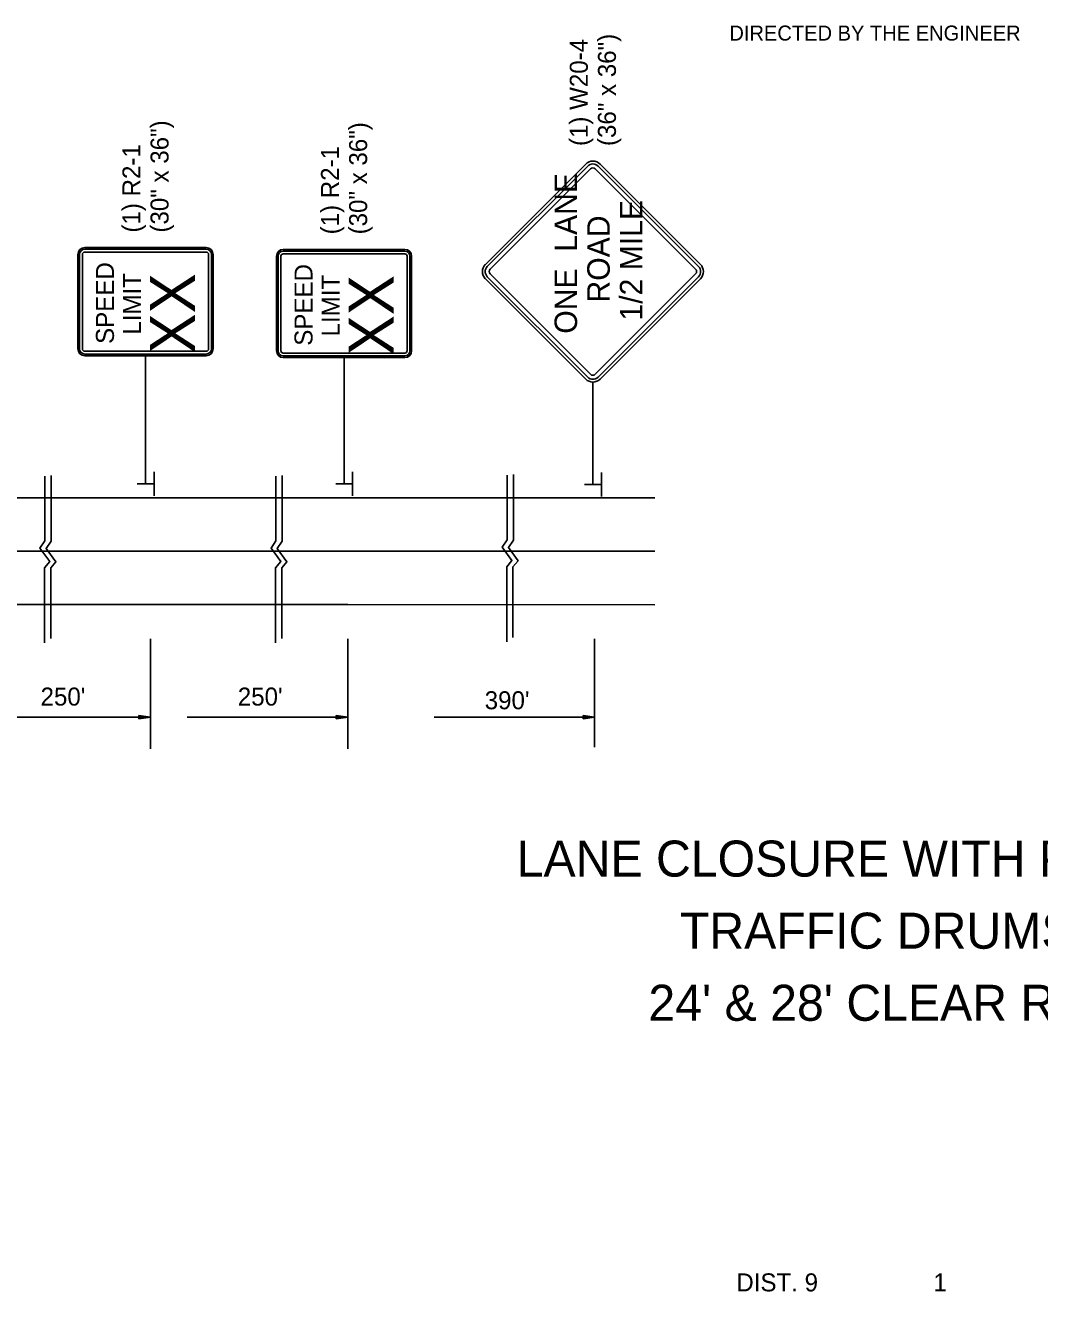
# Model space of a CAD drawing. Extents: x 1930579 to 1939784, y 596179 to 597522.
# Drawn here: x 1937952 to 1938289.6, y 596238.1 to 596659.7 of the extents above; entities that cross this region are included whole.
import ezdxf

# ---------------------------------------------------------------- set-up
doc = ezdxf.new("R2010")
doc.units = 0
for name, color, linetype in [('Default', 7, 'Continuous'), ('P_TC_Signs_Permanent', 7, 'Continuous'), ('P_TC_Signs_Temporary', 7, 'Continuous'), ('R_Annotation', 7, 'Continuous')]:
    doc.layers.add(name, color=color, linetype=linetype)

msp = doc.modelspace()

# ---------------------------------------------------------------- linework, layer by layer
at = {"layer": 'Default'}
for p, q in [((1937994.84, 596511.1), (1937994.84, 596503.09)), ((1938060.94, 596511.04), (1938060.94, 596503.03)), ((1938143.76, 596510.87), (1938143.76, 596502.87)), ((1937994.72, 596507.12), (1937989.26, 596507.12)), ((1938060.82, 596507.06), (1938055.35, 596507.06)), ((1938143.65, 596506.89), (1938138.18, 596506.89)), ((1937444.6, 596502.47), (1938059.31, 596502.42)), ((1938059.31, 596502.42), (1938161.51, 596502.41)), ((1937443.89, 596484.68), (1938161.51, 596484.63)), ((1937444.38, 596466.89), (1938059.31, 596466.85)), ((1938059.31, 596466.85), (1938161.51, 596466.83)), ((1937993.66, 596418.83), (1937993.66, 596455.43)), ((1938059.31, 596418.83), (1938059.31, 596455.43)), ((1938141.5, 596419.4), (1938141.5, 596455.43)), ((1937993.66, 596429.42), (1937940.26, 596429.42)), ((1937989.82, 596429.99), (1937993.66, 596429.42)), ((1937989.82, 596429.99), (1937989.82, 596428.84)), ((1937989.82, 596429.9), (1937993.02, 596429.42)), ((1937989.82, 596429.8), (1937992.36, 596429.42)), ((1937989.82, 596429.7), (1937991.72, 596429.42)), ((1937989.82, 596429.6), (1937991.07, 596429.42)), ((1937989.82, 596429.51), (1937990.43, 596429.42)), ((1937989.82, 596428.84), (1937993.66, 596429.42)), ((1937989.82, 596429.23), (1937991.07, 596429.42)), ((1937989.82, 596429.04), (1937992.36, 596429.42)), ((1937989.82, 596428.94), (1937993.02, 596429.42)), ((1937989.82, 596429.13), (1937991.72, 596429.42)), ((1937989.82, 596429.33), (1937990.43, 596429.42)), ((1938059.31, 596429.42), (1938005.91, 596429.42)), ((1938055.48, 596429.99), (1938059.31, 596429.42)), ((1938055.48, 596429.99), (1938055.48, 596428.84)), ((1938055.48, 596429.9), (1938058.67, 596429.42)), ((1938055.48, 596429.8), (1938058.01, 596429.42)), ((1938055.48, 596429.7), (1938057.37, 596429.42)), ((1938055.48, 596429.6), (1938056.72, 596429.42)), ((1938055.48, 596429.51), (1938056.08, 596429.42)), ((1938055.48, 596428.84), (1938059.31, 596429.42)), ((1938055.48, 596429.23), (1938056.72, 596429.42)), ((1938055.48, 596429.04), (1938058.01, 596429.42)), ((1938055.48, 596428.94), (1938058.67, 596429.42)), ((1938055.48, 596429.13), (1938057.37, 596429.42)), ((1938055.48, 596429.33), (1938056.08, 596429.42)), ((1938141.5, 596429.42), (1938088.1, 596429.42)), ((1938137.66, 596429.99), (1938141.5, 596429.42)), ((1938137.66, 596429.99), (1938137.66, 596428.84)), ((1938137.66, 596429.9), (1938140.86, 596429.42)), ((1938137.66, 596429.8), (1938140.2, 596429.42)), ((1938137.66, 596429.7), (1938139.56, 596429.42)), ((1938137.66, 596429.6), (1938138.91, 596429.42)), ((1938137.66, 596429.51), (1938138.27, 596429.42)), ((1938137.66, 596428.84), (1938141.5, 596429.42)), ((1938137.66, 596429.23), (1938138.91, 596429.42)), ((1938137.66, 596429.04), (1938140.2, 596429.42)), ((1938137.66, 596428.94), (1938140.86, 596429.42)), ((1938137.66, 596429.13), (1938139.56, 596429.42)), ((1938137.66, 596429.33), (1938138.27, 596429.42))]:
    msp.add_line(p, q, dxfattribs=at)
for points in [[(1937958.53, 596509.62), (1937958.53, 596488.1), (1937956.87, 596485.63), (1937960.11, 596481.2), (1937958.4, 596479.15), (1937958.4, 596454.12)], [(1937960.57, 596509.82), (1937960.57, 596488.01), (1937958.91, 596485.54), (1937962.15, 596481.11), (1937960.45, 596479.07), (1937960.44, 596455.56)], [(1938035.43, 596509.62), (1938035.43, 596488.1), (1938033.77, 596485.63), (1938037.01, 596481.2), (1938035.3, 596479.15), (1938035.3, 596454.12)], [(1938037.48, 596509.82), (1938037.48, 596488.01), (1938035.82, 596485.54), (1938039.05, 596481.11), (1938037.35, 596479.07), (1938037.34, 596455.56)], [(1938112.41, 596509.96), (1938112.41, 596488.44), (1938110.75, 596485.97), (1938113.98, 596481.54), (1938112.28, 596479.49), (1938112.27, 596454.47)], [(1938114.45, 596510.16), (1938114.45, 596488.35), (1938112.79, 596485.88), (1938116.03, 596481.45), (1938114.32, 596479.41), (1938114.32, 596455.91)]]:
    msp.add_lwpolyline(points, dxfattribs=at)
at = {"layer": 'P_TC_Signs_Permanent'}
for p, q in [((1938012.24, 596585.74), (1937971.74, 596585.74)), ((1938012.24, 596585.17), (1937971.74, 596585.17)), ((1938078.34, 596585.13), (1938037.84, 596585.13)), ((1937969.49, 596583.49), (1937969.49, 596551.99)), ((1937970.05, 596583.49), (1937970.05, 596551.99)), ((1937970.99, 596583.49), (1937970.99, 596551.99)), ((1938012.24, 596584.24), (1937971.74, 596584.24)), ((1938012.99, 596551.99), (1938012.99, 596583.49)), ((1938013.93, 596551.99), (1938013.93, 596583.49)), ((1938014.49, 596551.99), (1938014.49, 596583.49)), ((1938035.59, 596582.88), (1938035.59, 596551.38)), ((1938036.15, 596582.88), (1938036.15, 596551.38)), ((1938037.09, 596582.88), (1938037.09, 596551.38)), ((1938078.34, 596584.57), (1938037.84, 596584.57)), ((1938078.34, 596583.63), (1938037.84, 596583.63)), ((1938079.09, 596551.38), (1938079.09, 596582.88)), ((1938080.03, 596551.38), (1938080.03, 596582.88)), ((1938080.59, 596551.38), (1938080.59, 596582.88)), ((1937971.74, 596551.24), (1938012.24, 596551.24)), ((1937971.74, 596550.3), (1938012.24, 596550.3)), ((1937971.74, 596549.74), (1938012.24, 596549.74)), ((1938037.84, 596550.63), (1938078.34, 596550.63)), ((1938037.84, 596549.7), (1938078.34, 596549.7)), ((1938037.84, 596549.13), (1938078.34, 596549.13))]:
    msp.add_line(p, q, dxfattribs=at)
for centre, radius, start, end in [((1937971.74, 596583.49), 2.25, 90, 180), ((1937971.74, 596583.49), 1.69, 90, 180), ((1938012.24, 596583.49), 2.25, 360, 90), ((1938012.24, 596583.49), 1.69, 360, 90), ((1938037.84, 596582.88), 2.25, 90, 180), ((1938078.34, 596582.88), 2.25, 360, 90), ((1937971.74, 596583.49), 0.75, 90, 180), ((1938012.24, 596583.49), 0.75, 360, 90), ((1938037.84, 596582.88), 1.69, 90, 180), ((1938037.84, 596582.88), 0.75, 90, 180), ((1938078.34, 596582.88), 1.69, 360, 90), ((1938078.34, 596582.88), 0.75, 360, 90), ((1937971.74, 596551.99), 2.25, 180, 270), ((1937971.74, 596551.99), 1.69, 180, 270), ((1937971.74, 596551.99), 0.75, 180, 270), ((1938012.24, 596551.99), 2.25, 270, 360), ((1938012.24, 596551.99), 1.69, 270, 360), ((1938012.24, 596551.99), 0.75, 270, 360), ((1938037.84, 596551.38), 2.25, 180, 270), ((1938037.84, 596551.38), 1.69, 180, 270), ((1938037.84, 596551.38), 0.75, 180, 270), ((1938078.34, 596551.38), 2.25, 270, 360), ((1938078.34, 596551.38), 1.69, 270, 360), ((1938078.34, 596551.38), 0.75, 270, 360)]:
    msp.add_arc(centre, radius, start, end, dxfattribs=at)
at = {"layer": 'P_TC_Signs_Temporary'}
for p, q in [((1938105.12, 596580.15), (1938138.53, 596613.56)), ((1938105.78, 596579.48), (1938139.19, 596612.89)), ((1938106.71, 596578.56), (1938140.12, 596611.97)), ((1938141.71, 596611.97), (1938175.12, 596578.56)), ((1938142.64, 596612.89), (1938176.05, 596579.48)), ((1938143.3, 596613.56), (1938176.71, 596580.15)), ((1938140.12, 596543.55), (1938106.71, 596576.96)), ((1938175.12, 596576.96), (1938141.71, 596543.55)), ((1938138.53, 596541.96), (1938105.12, 596575.37)), ((1938139.19, 596542.63), (1938105.78, 596576.04)), ((1938176.05, 596576.04), (1938142.64, 596542.63)), ((1938176.71, 596575.37), (1938143.3, 596541.96))]:
    msp.add_line(p, q, dxfattribs=at)
for centre, radius, start, end in [((1938140.91, 596611.17), 3.38, 45, 135), ((1938140.91, 596611.17), 2.44, 45, 135), ((1938140.91, 596611.17), 1.12, 45, 135), ((1938107.5, 596577.76), 3.38, 135, 225), ((1938107.5, 596577.76), 2.44, 135, 225), ((1938107.5, 596577.76), 1.13, 135, 225), ((1938174.32, 596577.76), 1.13, 315, 45), ((1938174.32, 596577.76), 2.44, 315, 45), ((1938174.32, 596577.76), 3.38, 315, 45), ((1938140.91, 596544.35), 1.12, 225, 315), ((1938140.91, 596544.35), 3.38, 225, 315), ((1938140.91, 596544.35), 2.44, 225, 315)]:
    msp.add_arc(centre, radius, start, end, dxfattribs=at)
at = {"layer": 'R_Annotation'}
for p, q in [((1937991.99, 596507.12), (1937991.99, 596549.74)), ((1938058.09, 596507.06), (1938058.09, 596549.13)), ((1938140.91, 596506.89), (1938140.91, 596540.97))]:
    msp.add_line(p, q, dxfattribs=at)

# ---------------------------------------------------------------- texts
at = {"layer": 'Default'}
for s, height, p in [("250'", 6, (1937957.06, 596433.25)), ("250'", 6, (1938022.71, 596433.25)), ("390'", 6, (1938104.9, 596432.02)), ('LANE CLOSURE WITH PORTABLE TRAFFIC SIGNAL SYSTEM &', 12, (1938115.55, 596376.3)), ('TRAFFIC DRUMS FOR HYDRODEMOLITION BRIDGES', 12, (1938169.88, 596352.3)), ("24' & 28' CLEAR ROADWAY ON THE BRIDGE DECKS", 12, (1938159.39, 596328.3))]:
    msp.add_text(s, height=height, rotation=360, dxfattribs=at).set_placement(p)
at = {"layer": 'P_TC_Signs_Permanent'}
for s, height, p in [('SPEED', 6, (1937981.49, 596553.67)), ('LIMIT', 6, (1937990.49, 596556.76)), ('XX', 15, (1938008.49, 596550.44)), ('SPEED', 6, (1938047.59, 596553.06)), ('LIMIT', 6, (1938056.59, 596556.15)), ('XX', 15, (1938074.59, 596549.83))]:
    msp.add_text(s, height=height, rotation=90, dxfattribs=at).set_placement(p)
at = {"layer": 'P_TC_Signs_Temporary'}
for s, p in [('ONE  LANE', (1938135.66, 596557.06)), ('1/2 MILE', (1938157.41, 596561.45)), ('ROAD', (1938146.54, 596567.45))]:
    msp.add_text(s, height=7.5, rotation=90, dxfattribs=at).set_placement(p)
at = {"layer": 'R_Annotation'}
for s, height, rotation, p in [('DIRECTED BY THE ENGINEER', 5, 360, (1938186.35, 596654.66)), ('(1) W20-4', 6, 90, (1938139.23, 596619.55)), ('(36" x 36")', 6, 90, (1938148.59, 596619.55)), ('(30" x 36")', 5.9996, 90, (1937999.67, 596590.74)), ('(30" x 36")', 5.9996, 90, (1938065.77, 596590.13)), ('(1) R2-1', 6, 90, (1937990.31, 596590.74)), ('(1) R2-1', 6, 90, (1938056.41, 596590.13)), ('DIST. 9', 6, 360, (1938188.67, 596238.2)), ('1', 6, 360, (1938254.25, 596238.2))]:
    msp.add_text(s, height=height, rotation=rotation, dxfattribs=at).set_placement(p)

doc.saveas('drawing.dxf')
